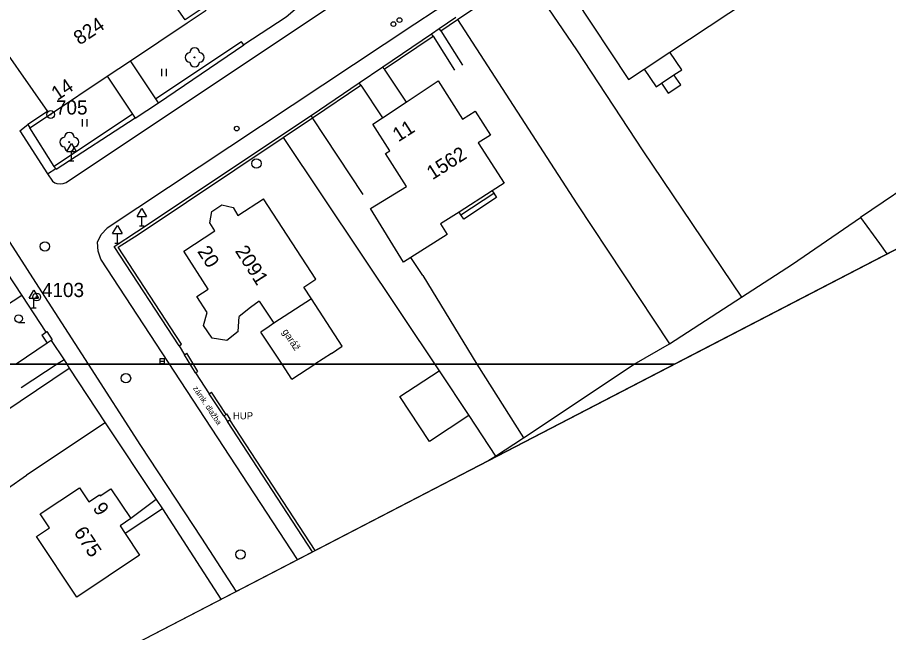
# Model space of a CAD drawing. Extents: x -493753 to -49290, y -1127285 to -112654.
# Drawn here: x -493060.6 to -492968.4, y -1127028.4 to -1126963.3 of the extents above; entities that cross this region are included whole.
import ezdxf

# ---------------------------------------------------------------- set-up
doc = ezdxf.new("R2010")
doc.units = 0
for name, color, linetype in [('Vrstva 1', 7, 'Continuous'), ('Vrstva 10', 7, 'Continuous'), ('Vrstva 11', 7, 'Continuous'), ('Vrstva 22', 7, 'Continuous'), ('Vrstva 24', 7, 'Continuous'), ('Vrstva 27', 7, 'Continuous'), ('Vrstva 28', 7, 'Continuous'), ('Vrstva 34', 7, 'Continuous'), ('Vrstva 36', 7, 'Continuous'), ('Vrstva 40', 7, 'Continuous'), ('Vrstva 41', 7, 'Continuous'), ('Vrstva 42', 7, 'Continuous'), ('Vrstva 43', 7, 'Continuous'), ('Vrstva 44', 7, 'Continuous'), ('Vrstva 5', 7, 'Continuous'), ('Vrstva 60', 7, 'Continuous'), ('Vrstva 63', 7, 'Continuous'), ('Vrstva 7', 7, 'Continuous'), ('Vrstva 8', 7, 'Continuous')]:
    doc.layers.add(name, color=color, linetype=linetype)

msp = doc.modelspace()

# ---------------------------------------------------------------- linework, layer by layer
at = {"layer": 'Vrstva 1'}
msp.add_lwpolyline([(-493753.129, -1126773.634), (-493540.881, -1127284.865), (-492737.61, -1126868.64), (-492950.39, -1126535.73)], dxfattribs=at)
at = {"layer": 'Vrstva 10'}
for p, q in [((-492988.97, -1126944.41), (-493018.54, -1126964.04)), ((-493055.45, -1126980.77), (-493006.11, -1126947.86)), ((-493018.54, -1126964.04), (-493051.1, -1126985.6)), ((-493060.34, -1126975.3), (-493059.49, -1126974.66)), ((-493060.34, -1126975.3), (-493057.41, -1126979.87)), ((-493057.41, -1126979.87), (-493056.87, -1126980.64)), ((-493030.965, -1127020.646), (-493051.76, -1126988.89))]:
    msp.add_line(p, q, dxfattribs=at)
for points in [[(-493053.08, -1127000), (-493058.01, -1126992.34), (-493066.27, -1126979.55), (-493076.27, -1126964), (-493078.5, -1126963.93)], [(-493016.62, -1126965.3), (-493014.34, -1126968.9)], [(-493015.8, -1126964.74), (-493013.49, -1126968.37)], [(-493021.78, -1126968.8), (-493019.48, -1126972.27)], [(-493024.26, -1126970.48), (-493021.98, -1126973.93)], [(-493056.87, -1126980.64), (-493056.65, -1126980.8), (-493056.41, -1126980.9)], [(-493056.41, -1126980.9), (-493056.08, -1126980.92), (-493055.75, -1126980.88), (-493055.45, -1126980.77)], [(-493052.12, -1126987.07), (-493051.74, -1126986.26), (-493051.1, -1126985.6)], [(-493051.76, -1126988.89), (-493052.05, -1126988.03), (-493052.12, -1126987.07)], [(-493060.13, -1126992.71), (-493063.82, -1126995.14)], [(-493057.44, -1126997.77), (-493060.74, -1126999.98)], [(-493055.66, -1126999.53), (-493056.38, -1127000)], [(-493056.38, -1127000), (-493060.21, -1127002.5)], [(-493037.434, -1127023.998), (-493041.07, -1127018.4), (-493047.55, -1127008.59), (-493053.08, -1127000)], [(-493045.92, -1127014.29), (-493048.59, -1127016.32)], [(-493045.25, -1127015.29), (-493049.18, -1127017.9)]]:
    msp.add_lwpolyline(points, dxfattribs=at)
at = {"layer": 'Vrstva 11'}
for p, q in [((-493048.14, -1126973.97), (-493045.67, -1126972.35)), ((-493057.41, -1126979.87), (-493056.54, -1126979.31)), ((-493029.49, -1126993.07), (-493033.46, -1126995.65))]:
    msp.add_line(p, q, dxfattribs=at)
for points in [[(-493014.05, -1126963.56), (-493001.42, -1126983.03)], [(-493001.45, -1126966.74), (-492994.42, -1126977.42)], [(-492990.31, -1126968.85), (-492991.57, -1126966.99)], [(-492994.29, -1126968.8), (-492993.02, -1126970.68)], [(-492991.13, -1126969.41), (-492990.31, -1126968.85)], [(-492992.44, -1126970.29), (-492991.13, -1126969.41)], [(-492990.42, -1126970.45), (-492991.13, -1126969.41)], [(-492993.02, -1126970.68), (-492992.44, -1126970.29)], [(-492992.44, -1126970.29), (-492991.73, -1126971.34)], [(-492991.73, -1126971.34), (-492990.42, -1126970.45)], [(-493032.48, -1126976.02), (-493015.98, -1127000.68)], [(-492994.42, -1126977.42), (-492983.99, -1126992.91)], [(-492964.31, -1126979.7), (-492971.4, -1126984.48)], [(-493013.67, -1126984.21), (-493010.19, -1126981.9)], [(-493010.36, -1126981.66), (-493010.19, -1126981.9)], [(-493010.19, -1126981.9), (-493009.9, -1126982.35)], [(-493029.49, -1126993.07), (-493030.29, -1126991.84), (-493029.03, -1126991.01), (-493034.57, -1126982.51)], [(-493009.9, -1126982.35), (-493013.37, -1126984.65)], [(-493001.42, -1126983.03), (-492991.62, -1126997.82)], [(-493013.67, -1126984.21), (-493013.87, -1126983.9)], [(-493013.37, -1126984.65), (-493013.67, -1126984.21)], [(-492978.59, -1126989.43), (-492971.4, -1126984.48)], [(-492971.4, -1126984.48), (-492969.4, -1126987.23)], [(-492969.4, -1126987.23), (-492968.595, -1126988.328)], [(-493017.71, -1126990.62), (-493018.98, -1126988.72)], [(-492983.99, -1126992.91), (-492978.59, -1126989.43)], [(-493017.71, -1126990.62), (-493011.99, -1127000)], [(-493026.23, -1126998.08), (-493029.49, -1126993.07)], [(-492991.62, -1126997.82), (-492983.99, -1126992.91)], [(-493035.02, -1126993.31), (-493035.95, -1126993.99)], [(-493035.02, -1126993.31), (-493033.46, -1126995.65)], [(-493033.46, -1126995.65), (-493033.96, -1126996.02)], [(-492995.36, -1127000), (-492991.62, -1126997.82)], [(-493027.38, -1126998.85), (-493026.23, -1126998.08)], [(-493075.9, -1127014.38), (-493055.1, -1127000.4)], [(-493011.99, -1127000), (-493007.05, -1127007.76)], [(-493007.05, -1127007.76), (-492995.36, -1127000)], [(-493020.14, -1127003.41), (-493015.98, -1127000.68)], [(-493015.98, -1127000.68), (-493012.85, -1127005.43)], [(-493017.01, -1127008.17), (-493020.14, -1127003.41)], [(-493012.85, -1127005.43), (-493017.01, -1127008.17)], [(-493012.85, -1127005.43), (-493010.02, -1127009.7)], [(-493010.02, -1127009.7), (-493007.05, -1127007.76)], [(-493010.714, -1127010.152), (-493010.02, -1127009.7)], [(-493073.75, -1127021.61), (-493059.64, -1127011.71)]]:
    msp.add_lwpolyline(points, dxfattribs=at)
at = {"layer": 'Vrstva 22'}
for centre in [(-493041.84, -1126967.55), (-493055.1, -1126976.5)]:
    msp.add_circle(centre, 0.05, dxfattribs=at)
for centre, start, end in [((-493042.34, -1126967.55), 90, 270), ((-493041.84, -1126967.05), 0, 180), ((-493041.34, -1126967.55), 270, 90), ((-493041.84, -1126968.05), 180, 0), ((-493055.1, -1126976), 0, 180), ((-493055.6, -1126976.5), 90, 270), ((-493054.6, -1126976.5), 270, 90), ((-493055.1, -1126977), 180, 0)]:
    msp.add_arc(centre, 0.5, start, end, dxfattribs=at)
at = {"layer": 'Vrstva 24'}
for p, q in [((-493058.02, -1126996.91), (-493057.44, -1126997.77)), ((-493057.48, -1126996.54), (-493056.9, -1126997.4)), ((-493038.77, -1127005.46), (-493038.38, -1127006.05))]:
    msp.add_line(p, q, dxfattribs=at)
for points in [[(-493058.02, -1126996.91), (-493057.58, -1126996.61), (-493057.48, -1126996.54)], [(-493056.9, -1126997.4), (-493057.01, -1126997.48), (-493057.44, -1126997.77)], [(-493038.77, -1127005.46), (-493038.51, -1127005.3), (-493038.43, -1127005.24)], [(-493038.05, -1127005.83), (-493038.43, -1127005.24)], [(-493038.38, -1127006.05), (-493038.13, -1127005.88), (-493038.05, -1127005.83)]]:
    msp.add_lwpolyline(points, dxfattribs=at)
at = {"layer": 'Vrstva 27'}
msp.add_line((-493045.53, -1126999.67), (-493045.03, -1126999.67), dxfattribs=at)
msp.add_lwpolyline([(-493045.53, -1126999.92), (-493045.03, -1126999.92), (-493045.03, -1126999.42), (-493045.53, -1126999.42)], close=True, dxfattribs=at)
for centre in [(-493035.3, -1126978.77), (-493057.69, -1126987.54), (-493049.11, -1127001.47), (-493037, -1127020.11)]:
    msp.add_circle(centre, 0.5, dxfattribs=at)
at = {"layer": 'Vrstva 28'}
for centre in [(-493020.17, -1126963.61), (-493020.81, -1126964.03), (-493037.39, -1126975.08)]:
    msp.add_circle(centre, 0.25, dxfattribs=at)
at = {"layer": 'Vrstva 34'}
for p, q in [((-493055.36, -1126977.49), (-493054.86, -1126976.64)), ((-493054.86, -1126976.64), (-493054.36, -1126977.49)), ((-493055.36, -1126977.49), (-493054.36, -1126977.49)), ((-493054.86, -1126978.49), (-493054.86, -1126977.49)), ((-493055.11, -1126978.49), (-493054.61, -1126978.49)), ((-493047.94, -1126984.37), (-493047.44, -1126983.52)), ((-493047.44, -1126983.52), (-493046.94, -1126984.37)), ((-493047.94, -1126984.37), (-493046.94, -1126984.37)), ((-493047.44, -1126985.37), (-493047.44, -1126984.37)), ((-493050.52, -1126986.18), (-493050.02, -1126985.33)), ((-493050.02, -1126985.33), (-493049.52, -1126986.18)), ((-493047.69, -1126985.37), (-493047.19, -1126985.37)), ((-493050.52, -1126986.18), (-493049.52, -1126986.18)), ((-493050.02, -1126987.18), (-493050.02, -1126986.18)), ((-493050.27, -1126987.18), (-493049.77, -1126987.18)), ((-493059.36, -1126993.02), (-493058.86, -1126992.17)), ((-493058.86, -1126992.17), (-493058.36, -1126993.02)), ((-493059.36, -1126993.02), (-493058.36, -1126993.02)), ((-493058.86, -1126994.02), (-493058.86, -1126993.02)), ((-493059.11, -1126994.02), (-493058.61, -1126994.02))]:
    msp.add_line(p, q, dxfattribs=at)
at = {"layer": 'Vrstva 36'}
for p, q in [((-493045.32, -1126969.52), (-493045.32, -1126968.77)), ((-493044.82, -1126969.52), (-493044.82, -1126968.77)), ((-493053.72, -1126974.84), (-493053.72, -1126974.09)), ((-493053.22, -1126974.84), (-493053.22, -1126974.09)), ((-493060.472, -1126995.57), (-493059.822, -1126995.567))]:
    msp.add_line(p, q, dxfattribs=at)
msp.add_circle((-493060.472, -1126995.167), 0.403, dxfattribs=at)
at = {"layer": 'Vrstva 5'}
for p, q in [((-493002.01, -1126960.71), (-492995.93, -1126969.88)), ((-493016.08, -1126970.02), (-493013.5, -1126974.07)), ((-493013.5, -1126974.07), (-493012.18, -1126973.22)), ((-493012.18, -1126973.22), (-493010.55, -1126975.78)), ((-493021.19, -1126977.42), (-493022.99, -1126974.61)), ((-493010.55, -1126975.78), (-493011.83, -1126976.6)), ((-493011.83, -1126976.6), (-493009.11, -1126980.86)), ((-493021.66, -1126977.72), (-493021.19, -1126977.42)), ((-493019.43, -1126981.21), (-493021.66, -1126977.72)), ((-493023.22, -1126983.52), (-493019.43, -1126981.21)), ((-493037.27, -1126984.28), (-493034.57, -1126982.51)), ((-493040.25, -1126985.05), (-493040.02, -1126983.83)), ((-493040.02, -1126983.83), (-493038.97, -1126983.15)), ((-493038.97, -1126983.15), (-493037.78, -1126983.42)), ((-493037.78, -1126983.42), (-493037.27, -1126984.28)), ((-493019.73, -1126989.2), (-493023.22, -1126983.52)), ((-493042.98, -1126988.04), (-493039.7, -1126985.89)), ((-493039.7, -1126985.89), (-493040.25, -1126985.05)), ((-493015.84, -1126985.15), (-493015.13, -1126986.26)), ((-493040.4, -1126992.04), (-493042.98, -1126988.04)), ((-493041.61, -1126992.84), (-493040.4, -1126992.04)), ((-493040.5, -1126994.54), (-493041.61, -1126992.84)), ((-493035.95, -1126993.99), (-493037.14, -1126994.94)), ((-493040.89, -1126995.9), (-493040.5, -1126994.54)), ((-493037.24, -1126996.53), (-493037.14, -1126994.94)), ((-493040, -1126997.23), (-493040.89, -1126995.9)), ((-493033.96, -1126996.02), (-493034.84, -1126996.59)), ((-493037.24, -1126996.53), (-493038.43, -1126997.48)), ((-493038.43, -1126997.48), (-493040, -1126997.23)), ((-493027.38, -1126998.85), (-493029.14, -1127000)), ((-493031.56, -1127001.59), (-493029.14, -1127000)), ((-493058.19, -1127015.83), (-493054.02, -1127013.07)), ((-493054.02, -1127013.07), (-493053.04, -1127014.55)), ((-493051.83, -1127013.91), (-493050.7, -1127013.16)), ((-493050.7, -1127013.16), (-493048.59, -1127016.32)), ((-493053.04, -1127014.55), (-493051.91, -1127013.8)), ((-493051.91, -1127013.8), (-493051.83, -1127013.91)), ((-493057.2, -1127017.31), (-493058.19, -1127015.83)), ((-493048.59, -1127016.32), (-493049.73, -1127017.08)), ((-493058.57, -1127018.22), (-493057.2, -1127017.31)), ((-493054.32, -1127024.62), (-493058.57, -1127018.22)), ((-493047.66, -1127020.19), (-493054.32, -1127024.62))]:
    msp.add_line(p, q, dxfattribs=at)
for points in [[(-493042.85, -1126963.57), (-493049.87, -1126953.52)], [(-492991.57, -1126966.99), (-492977, -1126957.33)], [(-493042.62, -1126963.89), (-493040.62, -1126962.56), (-493040.85, -1126962.23), (-493042.85, -1126963.57)], [(-493064.22, -1126963.55), (-493063.89, -1126964.03), (-493057.42, -1126973.28)], [(-493057.19, -1126973.61), (-493051.09, -1126969.54), (-493048.64, -1126967.91), (-493042.62, -1126963.89)], [(-492994.29, -1126968.8), (-492991.57, -1126966.99)], [(-492995.93, -1126969.88), (-492994.29, -1126968.8)], [(-493022.99, -1126974.61), (-493021.98, -1126973.93), (-493019.48, -1126972.27), (-493016.08, -1126970.02)], [(-493057.42, -1126973.28), (-493059.49, -1126974.66), (-493059.27, -1126975), (-493057.19, -1126973.61)], [(-493009.11, -1126980.86), (-493010.36, -1126981.66)], [(-493010.36, -1126981.66), (-493013.87, -1126983.9)], [(-493013.87, -1126983.9), (-493015.84, -1126985.15)], [(-493015.13, -1126986.26), (-493018.98, -1126988.72)], [(-493018.98, -1126988.72), (-493019.73, -1126989.2)], [(-493032.6, -1127000), (-493034.84, -1126996.59)], [(-493031.56, -1127001.59), (-493032.6, -1127000)], [(-493049.73, -1127017.08), (-493049.18, -1127017.9), (-493047.66, -1127020.19)]]:
    msp.add_lwpolyline(points, dxfattribs=at)
at = {"layer": 'Vrstva 60'}
msp.add_line((-493125, -1127069.371), (-492991.121, -1127000), dxfattribs=at)
for points in [[(-492991.121, -1127000), (-492737.61, -1126868.64), (-492950.39, -1126535.73), (-493125, -1126587.478)], [(-493125, -1126587.478), (-493125, -1127000), (-492991.121, -1127000)], [(-492991.121, -1127000), (-493125, -1127000), (-493125, -1127069.371)]]:
    msp.add_lwpolyline(points, dxfattribs=at)
at = {"layer": 'Vrstva 63'}
for centre, radius in [((-493057.08, -1126973.59), 0.412), ((-493057.08, -1126973.59), 0.05), ((-493058.56, -1126992.89), 0.412), ((-493058.56, -1126992.89), 0.05)]:
    msp.add_circle(centre, radius, dxfattribs=at)
at = {"layer": 'Vrstva 7'}
for p, q in [((-493014.05, -1126963.56), (-493006.91, -1126958.72)), ((-493015.96, -1126964.49), (-493014.22, -1126963.31)), ((-493015.8, -1126964.74), (-493014.05, -1126963.56)), ((-493015.8, -1126964.74), (-493015.96, -1126964.49)), ((-493021.95, -1126968.55), (-493016.79, -1126965.06)), ((-493021.78, -1126968.8), (-493016.62, -1126965.3)), ((-493016.62, -1126965.3), (-493016.79, -1126965.06)), ((-493021.78, -1126968.8), (-493021.95, -1126968.55)), ((-493029.53, -1126973.69), (-493024.43, -1126970.23)), ((-493029.37, -1126973.94), (-493024.26, -1126970.48)), ((-493024.26, -1126970.48), (-493024.43, -1126970.23)), ((-493047.98, -1126986.01), (-493029.53, -1126973.69)), ((-493029.37, -1126973.94), (-493029.53, -1126973.69)), ((-493048.14, -1126973.97), (-493056.48, -1126979.41)), ((-493050.35, -1126987.54), (-493047.98, -1126986.01)), ((-493049.93, -1126987.63), (-493047.83, -1126986.27)), ((-493043.49, -1126998.05), (-493050.35, -1126987.54)), ((-493043.24, -1126997.88), (-493049.93, -1126987.63)), ((-493043.49, -1126998.05), (-493043.24, -1126997.88)), ((-493042.92, -1126998.99), (-493042.67, -1126998.84)), ((-493041.75, -1127000.91), (-493042.92, -1126998.99)), ((-493041.49, -1127000.76), (-493042.67, -1126998.84)), ((-493041.75, -1127000.91), (-493041.49, -1127000.76)), ((-493040.3, -1127003.12), (-493040.05, -1127002.96)), ((-493038.77, -1127005.46), (-493040.3, -1127003.12)), ((-493038.51, -1127005.3), (-493040.05, -1127002.96)), ((-493029.366, -1127019.817), (-493038.38, -1127006.05)), ((-493029.098, -1127019.678), (-493038.13, -1127005.88)), ((-493051.31, -1127006.18), (-493059.64, -1127011.71))]:
    msp.add_line(p, q, dxfattribs=at)
for points in [[(-493007.08, -1126958.47), (-493006.91, -1126958.72), (-493001.45, -1126966.74)], [(-493036.65, -1126966.22), (-493036.87, -1126965.89), (-493045.95, -1126971.93)], [(-493045.67, -1126972.35), (-493036.65, -1126966.22)], [(-493045.95, -1126971.93), (-493048.64, -1126967.91)], [(-493051.09, -1126969.54), (-493048.41, -1126973.56)], [(-493045.67, -1126972.35), (-493045.95, -1126971.93)], [(-493048.41, -1126973.56), (-493056.7, -1126979.07)], [(-493048.41, -1126973.56), (-493048.14, -1126973.97)], [(-493047.83, -1126986.27), (-493032.48, -1126976.02), (-493029.37, -1126973.94)], [(-493024.01, -1126982.03), (-493029.37, -1126973.94)], [(-493056.7, -1126979.07), (-493059.27, -1126975)], [(-493056.48, -1126979.41), (-493056.54, -1126979.31), (-493056.7, -1126979.07)], [(-493067.92, -1126980.61), (-493061.74, -1126990.26), (-493060.13, -1126992.71), (-493057.58, -1126996.61)], [(-493057.01, -1126997.48), (-493055.66, -1126999.53), (-493055.36, -1127000)], [(-493055.36, -1127000), (-493055.1, -1127000.4), (-493051.31, -1127006.18), (-493045.92, -1127014.29), (-493045.25, -1127015.29), (-493039.057, -1127024.839)]]:
    msp.add_lwpolyline(points, dxfattribs=at)
at = {"layer": 'Vrstva 8'}
for p, q in [((-493016.79, -1126965.06), (-493015.96, -1126964.49)), ((-493024.43, -1126970.23), (-493021.95, -1126968.55)), ((-493043.49, -1126998.05), (-493042.92, -1126998.99)), ((-493041.75, -1127000.91), (-493040.3, -1127003.12))]:
    msp.add_line(p, q, dxfattribs=at)
msp.add_lwpolyline([(-493030.72, -1126962.06), (-493032.15, -1126963.28), (-493036.65, -1126966.22)], dxfattribs=at)

# ---------------------------------------------------------------- texts
at = {"layer": 'Vrstva 40'}
msp.add_text('zámk. dlažba', height=0.6, rotation=303.75813, dxfattribs=at).set_placement((-493042.045, -1127002.555))
at = {"layer": 'Vrstva 41'}
msp.add_text('garáž', height=0.75, rotation=303.27098, dxfattribs=at).set_placement((-493032.596, -1126996.551))
at = {"layer": 'Vrstva 42'}
msp.add_text('HUP', height=0.75, dxfattribs=at).set_placement((-493037.78, -1127005.815))
at = {"layer": 'Vrstva 43'}
for s, rotation, p in [('824', 33.70005, (-493054.019, -1126966.305)), ('1562', 32.53997, (-493016.682, -1126980.548)), ('2091', 302.53997, (-493037.615, -1126988.013)), ('675', 303.59075, (-493054.686, -1127017.762))]:
    msp.add_text(s, height=1.5, rotation=rotation, dxfattribs=at).set_placement(p)
at = {"layer": 'Vrstva 44'}
for s, rotation, p in [('14', 33.70005, (-493056.374, -1126972.168)), ('11', 32.54605, (-493020.294, -1126976.536)), ('20', 302.54605, (-493041.603, -1126988.063)), ('9', 303.59075, (-493052.673, -1127015.217))]:
    msp.add_text(s, height=1.5, rotation=rotation, dxfattribs=at).set_placement(p)
at = {"layer": 'Vrstva 63'}
for s, p in [(' 705', (-493057.08, -1126973.59)), (' 4103', (-493058.56, -1126992.89))]:
    msp.add_text(s, height=1.5, dxfattribs=at).set_placement(p)

doc.saveas('drawing.dxf')
